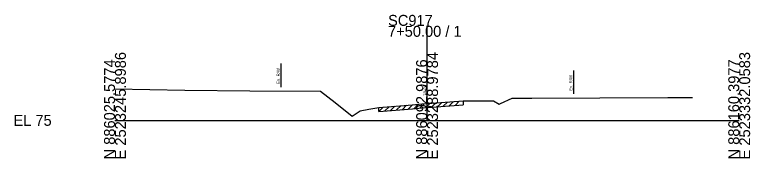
# Model space of a CAD drawing. Extents: x -26 to 218, y -10 to 12021.
# Drawn here: x -25.7 to 162.8, y 7490.3 to 7527 of the extents above; entities that cross this region are included whole.
import ezdxf

# ---------------------------------------------------------------- set-up
doc = ezdxf.new("R2010")
doc.units = 0
for name, color, linetype in [('RD_GPK_XS_Cell', 7, 'Continuous'), ('RD_XS_ExGround', 7, 'Continuous'), ('RD_XS_ExPaveRet', 7, 'Continuous'), ('RD_XS_ExRW', 7, 'Continuous'), ('RD_XS_TX_Elev_EX', 7, 'Continuous')]:
    doc.layers.add(name, color=color, linetype=linetype)

msp = doc.modelspace()

# ---------------------------------------------------------------- linework, layer by layer
at = {"layer": 'RD_GPK_XS_Cell'}
for p, q in [((80, 7500), (80, 7524.18)), ((0, 7500), (80, 7500)), ((80, 7500), (160, 7500))]:
    msp.add_line(p, q, dxfattribs=at)
at = {"layer": 'RD_XS_ExGround'}
for p, q in [((0, 7508.06), (17.87, 7507.76)), ((17.87, 7507.76), (34.53, 7507.59)), ((34.53, 7507.59), (52.68, 7507.46)), ((52.68, 7507.46), (56.45, 7504.6)), ((98.79, 7504.3), (101.82, 7505.67)), ((101.82, 7505.67), (103.61, 7505.67)), ((103.61, 7505.67), (106.82, 7505.72)), ((106.82, 7505.72), (141.68, 7505.89)), ((141.68, 7505.89), (148.02, 7505.83)), ((56.45, 7504.6), (60.84, 7501.09)), ((67.66, 7503.28), (76.23, 7503.99)), ((76.23, 7503.99), (78.63, 7504.19)), ((78.63, 7504.19), (80, 7504.3)), ((80, 7504.3), (88.15, 7504.91)), ((88.15, 7504.91), (89.27, 7505)), ((89.27, 7505), (96.28, 7504.98)), ((96.28, 7504.98), (97.06, 7504.98)), ((97.06, 7504.98), (98.48, 7504.17)), ((98.48, 7504.17), (98.79, 7504.3)), ((60.84, 7501.09), (61.83, 7501.79)), ((61.83, 7501.79), (62.82, 7502.46)), ((62.82, 7502.46), (65.06, 7502.83)), ((65.06, 7502.83), (67.66, 7503.28))]:
    msp.add_line(p, q, dxfattribs=at)
at = {"layer": 'RD_XS_ExPaveRet'}
for p, q in [((70.66, 7502.53), (71.75, 7503.62)), ((72.16, 7502.66), (73.25, 7503.75)), ((73.66, 7502.78), (74.75, 7503.87)), ((75.16, 7502.9), (76.25, 7503.99)), ((76.66, 7503.03), (77.75, 7504.12)), ((78.16, 7503.15), (79.24, 7504.24)), ((79.66, 7503.27), (80.74, 7504.35)), ((80, 7503.3), (88.15, 7503.91)), ((81.16, 7503.38), (82.24, 7504.47)), ((82.66, 7503.5), (83.74, 7504.58)), ((84.16, 7503.61), (85.24, 7504.69)), ((85.66, 7503.72), (86.74, 7504.81)), ((87.16, 7503.84), (88.24, 7504.92)), ((88.15, 7503.91), (89.27, 7504)), ((89.27, 7505), (89.27, 7504)), ((67.66, 7502.28), (68.75, 7503.37)), ((67.66, 7502.28), (67.66, 7503.28)), ((67.66, 7502.28), (76.23, 7502.99)), ((69.16, 7502.41), (70.25, 7503.5)), ((76.23, 7502.99), (78.63, 7503.19)), ((78.63, 7503.19), (80, 7503.3))]:
    msp.add_line(p, q, dxfattribs=at)
at = {"layer": 'RD_XS_ExRW'}
for p, q in [((42.5, 7514.53), (42.5, 7508.53)), ((117.5, 7512.77), (117.5, 7506.77))]:
    msp.add_line(p, q, dxfattribs=at)

# ---------------------------------------------------------------- texts
at = {"layer": 'RD_GPK_XS_Cell'}
for s, p in [('SC917', (70, 7524.18)), ('7+50.00 / 1', (70, 7521.38)), ('EL 75', (-26, 7498.6))]:
    msp.add_text(s, height=2.8, dxfattribs=at).set_placement(p)
for s, p in [('E 2523245.8986', (2.8, 7490)), ('E 2523288.9784', (82.8, 7490)), ('E 2523332.0583', (162.8, 7490)), ('N 886025.5774', (0, 7490)), ('N 886092.9876', (80, 7490)), ('N 886160.3977', (160, 7490))]:
    msp.add_text(s, height=2.8, rotation=90, dxfattribs=at).set_placement(p)
at = {"layer": 'RD_XS_ExRW'}
for p in [(42.25, 7509.32), (117.25, 7507.56)]:
    msp.add_text('Ex. R/W ', height=0.8, rotation=90, dxfattribs=at).set_placement(p)
at = {"layer": 'RD_XS_TX_Elev_EX'}
msp.add_text('79.30', height=0.8, rotation=90, dxfattribs=at).set_placement((79.9, 7506.3))

doc.saveas('drawing.dxf')
